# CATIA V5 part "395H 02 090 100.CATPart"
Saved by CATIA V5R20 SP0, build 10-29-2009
Part number: Part1
Source: Unknown
Bounding box of the stored display mesh (mm): x -46 to 46, y -46 to 45.804, z -51 to 51
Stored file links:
  C:\Users\Utente\Desktop\3D files 395H FORD\395H 02 090 100.CATPart
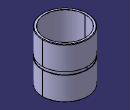
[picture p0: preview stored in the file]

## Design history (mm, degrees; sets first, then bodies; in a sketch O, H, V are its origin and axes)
Body1 (main body)
  Solid1 "PartBody": solid without history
